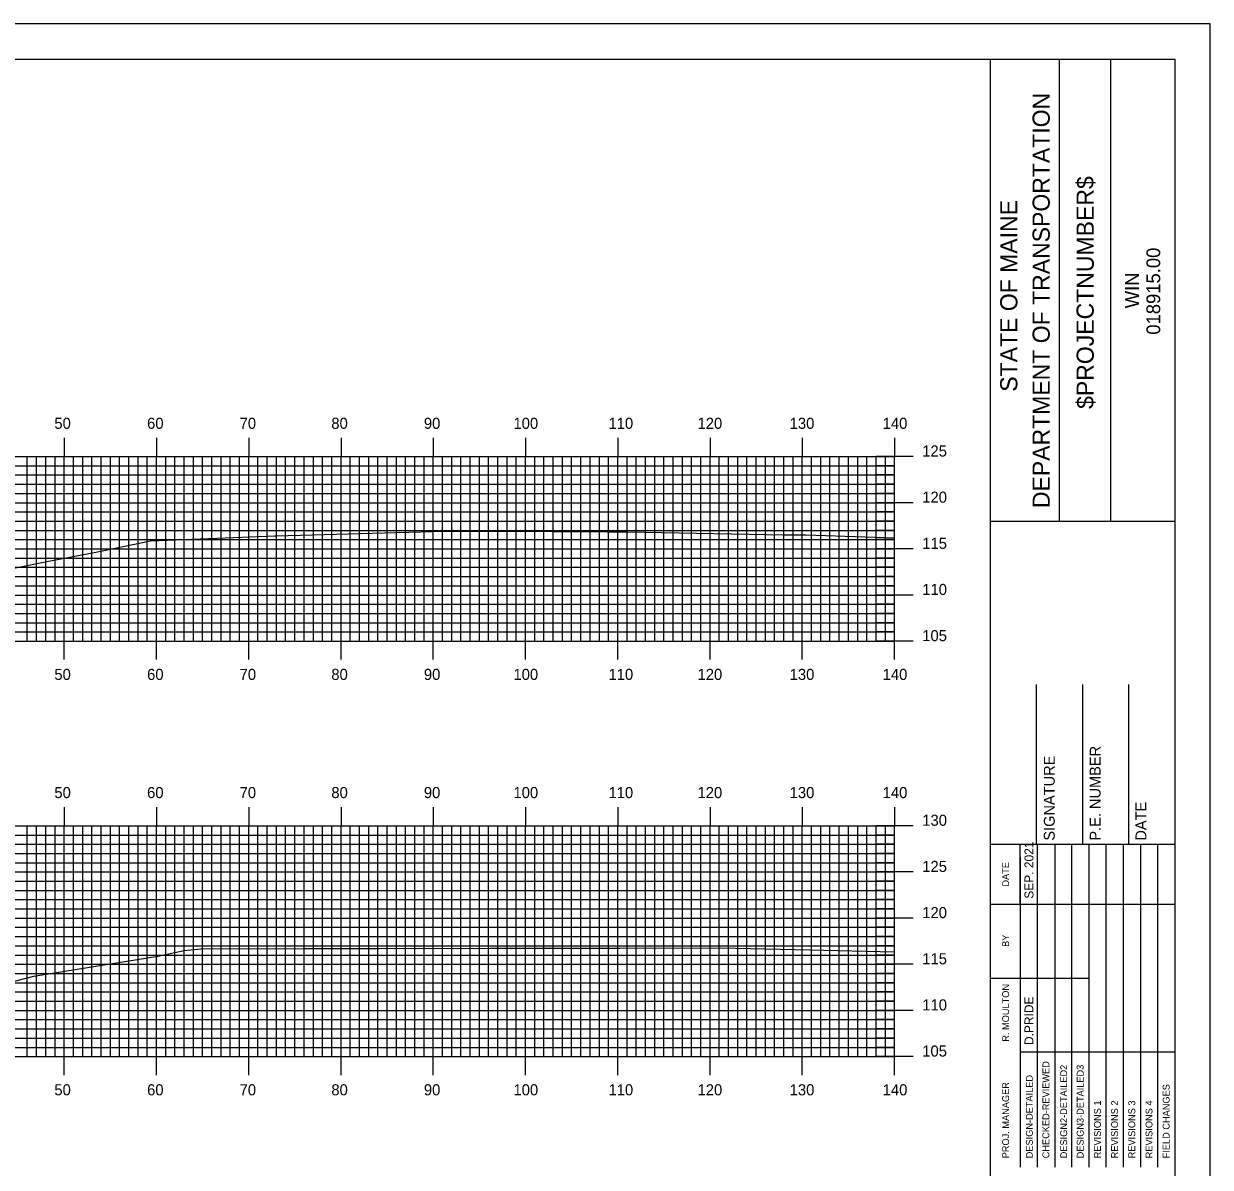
# Model space of a CAD drawing. Extents: x 844536 to 844879, y 363538 to 363758.
# Drawn here: x 844747.6 to 844876.2, y 363633.7 to 363757.6 of the extents above; entities that cross this region are included whole.
import ezdxf

# ---------------------------------------------------------------- set-up
doc = ezdxf.new("R2010")
doc.units = 0
for name, color, linetype in [('BORDER', 7, 'Continuous'), ('H_V ANNOTATION', 7, 'Continuous'), ('MAJOR', 7, 'Continuous'), ('MINOR', 7, 'Continuous'), ('PLOT BOUNDARY', 7, 'Continuous'), ('S_Roadway_Centerline', 7, 'Continuous')]:
    doc.layers.add(name, color=color, linetype=linetype)

msp = doc.modelspace()

# ---------------------------------------------------------------- linework, layer by layer
at = {"layer": 'BORDER'}
for p, q in [((844852.36, 363543.72), (844852.36, 363753.72)), ((844859.82, 363703.72), (844859.82, 363753.72)), ((844865.41, 363703.72), (844865.41, 363753.72)), ((844852.37, 363703.71), (844872.36, 363703.71)), ((844857.36, 363668.73), (844857.36, 363686.02)), ((844862.36, 363668.73), (844862.36, 363686.02)), ((844867.36, 363668.73), (844867.36, 363686.02)), ((844852.36, 363668.73), (844872.36, 363668.73))]:
    msp.add_line(p, q, dxfattribs=at)
msp.add_lwpolyline([(844552.36, 363543.72), (844872.36, 363543.72), (844872.36, 363753.72), (844552.36, 363753.72)], close=True, dxfattribs=at)
for points in [[(844855.59, 363662.23), (844855.59, 363668.73)], [(844857.46, 363633.73), (844857.46, 363668.73)], [(844859.32, 363668.73), (844859.32, 363633.73)], [(844861.19, 363633.73), (844861.19, 363668.73)], [(844863.05, 363633.73), (844863.05, 363668.73)], [(844864.91, 363633.73), (844864.91, 363668.73)], [(844866.78, 363633.73), (844866.78, 363668.73)], [(844868.64, 363633.73), (844868.64, 363668.73)], [(844870.5, 363633.73), (844870.5, 363668.73)], [(844855.6, 363633.73), (844855.6, 363667.31)], [(844852.36, 363662.23), (844872.36, 363662.23)], [(844852.36, 363654.23), (844855.6, 363654.23)], [(844855.59, 363654.23), (844863.05, 363654.23)], [(844855.59, 363646.23), (844872.36, 363646.23)]]:
    msp.add_lwpolyline(points, dxfattribs=at)
at = {"layer": 'MAJOR'}
for p, q in [((844751.96, 363712.73), (844751.96, 363710.72)), ((844761.96, 363712.73), (844761.96, 363710.72)), ((844771.96, 363712.73), (844771.96, 363710.72)), ((844781.96, 363712.73), (844781.96, 363710.72)), ((844791.96, 363712.73), (844791.96, 363710.72)), ((844801.96, 363712.73), (844801.96, 363710.72)), ((844811.96, 363712.73), (844811.96, 363710.72)), ((844821.96, 363712.73), (844821.96, 363710.72)), ((844831.96, 363712.73), (844831.96, 363710.72)), ((844841.96, 363712.73), (844841.96, 363710.72)), ((844561.96, 363710.72), (844841.96, 363710.72)), ((844561.96, 363710.72), (844841.96, 363710.72)), ((844751.96, 363690.72), (844751.96, 363710.72)), ((844761.96, 363690.72), (844761.96, 363710.72)), ((844771.96, 363690.72), (844771.96, 363710.72)), ((844781.96, 363690.72), (844781.96, 363710.72)), ((844791.96, 363690.72), (844791.96, 363710.72)), ((844801.96, 363690.72), (844801.96, 363710.72)), ((844811.96, 363690.72), (844811.96, 363710.72)), ((844821.96, 363690.72), (844821.96, 363710.72)), ((844831.96, 363690.72), (844831.96, 363710.72)), ((844843.97, 363710.72), (844839.96, 363710.72)), ((844841.96, 363690.72), (844841.96, 363710.72)), ((844841.96, 363690.72), (844841.96, 363710.72)), ((844561.96, 363705.72), (844841.96, 363705.72)), ((844843.97, 363705.72), (844839.96, 363705.72)), ((844561.96, 363700.72), (844841.96, 363700.72)), ((844843.97, 363700.72), (844839.96, 363700.72)), ((844561.96, 363695.72), (844841.96, 363695.72)), ((844843.97, 363695.72), (844839.96, 363695.72)), ((844561.96, 363690.72), (844841.96, 363690.72)), ((844561.96, 363690.72), (844841.96, 363690.72)), ((844751.96, 363688.72), (844751.96, 363690.72)), ((844761.96, 363688.72), (844761.96, 363690.72)), ((844771.96, 363688.72), (844771.96, 363690.72)), ((844781.96, 363688.72), (844781.96, 363690.72)), ((844791.96, 363688.72), (844791.96, 363690.72)), ((844801.96, 363688.72), (844801.96, 363690.72)), ((844811.96, 363688.72), (844811.96, 363690.72)), ((844821.96, 363688.72), (844821.96, 363690.72)), ((844831.96, 363688.72), (844831.96, 363690.72)), ((844843.97, 363690.72), (844839.96, 363690.72)), ((844841.96, 363688.72), (844841.96, 363690.72)), ((844751.96, 363672.73), (844751.96, 363670.72)), ((844761.96, 363672.73), (844761.96, 363670.72)), ((844771.96, 363672.73), (844771.96, 363670.72)), ((844781.96, 363672.73), (844781.96, 363670.72)), ((844791.96, 363672.73), (844791.96, 363670.72)), ((844801.96, 363672.73), (844801.96, 363670.72)), ((844811.96, 363672.73), (844811.96, 363670.72)), ((844821.96, 363672.73), (844821.96, 363670.72)), ((844831.96, 363672.73), (844831.96, 363670.72)), ((844841.96, 363672.73), (844841.96, 363670.72)), ((844561.96, 363670.72), (844841.96, 363670.72)), ((844561.96, 363670.72), (844841.96, 363670.72)), ((844751.96, 363645.72), (844751.96, 363670.72)), ((844761.96, 363645.72), (844761.96, 363670.72)), ((844771.96, 363645.72), (844771.96, 363670.72)), ((844781.96, 363645.72), (844781.96, 363670.72)), ((844791.96, 363645.72), (844791.96, 363670.72)), ((844801.96, 363645.72), (844801.96, 363670.72)), ((844811.96, 363645.72), (844811.96, 363670.72)), ((844821.96, 363645.72), (844821.96, 363670.72)), ((844831.96, 363645.72), (844831.96, 363670.72)), ((844843.97, 363670.72), (844839.96, 363670.72)), ((844841.96, 363645.72), (844841.96, 363670.72)), ((844841.96, 363645.72), (844841.96, 363670.72)), ((844561.96, 363665.72), (844841.96, 363665.72)), ((844843.97, 363665.72), (844839.96, 363665.72)), ((844561.96, 363660.72), (844841.96, 363660.72)), ((844843.97, 363660.72), (844839.96, 363660.72)), ((844561.96, 363655.72), (844841.96, 363655.72)), ((844843.97, 363655.72), (844839.96, 363655.72)), ((844561.96, 363650.72), (844841.96, 363650.72)), ((844843.97, 363650.72), (844839.96, 363650.72)), ((844561.96, 363645.72), (844841.96, 363645.72)), ((844561.96, 363645.72), (844841.96, 363645.72)), ((844751.96, 363643.72), (844751.96, 363645.72)), ((844761.96, 363643.72), (844761.96, 363645.72)), ((844771.96, 363643.72), (844771.96, 363645.72)), ((844781.96, 363643.72), (844781.96, 363645.72)), ((844791.96, 363643.72), (844791.96, 363645.72)), ((844801.96, 363643.72), (844801.96, 363645.72)), ((844811.96, 363643.72), (844811.96, 363645.72)), ((844821.96, 363643.72), (844821.96, 363645.72)), ((844831.96, 363643.72), (844831.96, 363645.72)), ((844843.97, 363645.72), (844839.96, 363645.72)), ((844841.96, 363643.72), (844841.96, 363645.72))]:
    msp.add_line(p, q, dxfattribs=at)
at = {"layer": 'MINOR'}
for p, q in [((844747.96, 363690.72), (844747.96, 363710.72)), ((844748.96, 363690.72), (844748.96, 363710.72)), ((844749.96, 363690.72), (844749.96, 363710.72)), ((844750.96, 363690.72), (844750.96, 363710.72)), ((844752.96, 363690.72), (844752.96, 363710.72)), ((844753.96, 363690.72), (844753.96, 363710.72)), ((844754.96, 363690.72), (844754.96, 363710.72)), ((844755.96, 363690.72), (844755.96, 363710.72)), ((844756.96, 363690.72), (844756.96, 363710.72)), ((844757.96, 363690.72), (844757.96, 363710.72)), ((844758.96, 363690.72), (844758.96, 363710.72)), ((844759.96, 363690.72), (844759.96, 363710.72)), ((844760.96, 363690.72), (844760.96, 363710.72)), ((844762.96, 363690.72), (844762.96, 363710.72)), ((844763.96, 363690.72), (844763.96, 363710.72)), ((844764.96, 363690.72), (844764.96, 363710.72)), ((844765.96, 363690.72), (844765.96, 363710.72)), ((844766.96, 363690.72), (844766.96, 363710.72)), ((844767.96, 363690.72), (844767.96, 363710.72)), ((844768.96, 363690.72), (844768.96, 363710.72)), ((844769.96, 363690.72), (844769.96, 363710.72)), ((844770.96, 363690.72), (844770.96, 363710.72)), ((844772.96, 363690.72), (844772.96, 363710.72)), ((844773.96, 363690.72), (844773.96, 363710.72)), ((844774.96, 363690.72), (844774.96, 363710.72)), ((844775.96, 363690.72), (844775.96, 363710.72)), ((844776.96, 363690.72), (844776.96, 363710.72)), ((844777.96, 363690.72), (844777.96, 363710.72)), ((844778.96, 363690.72), (844778.96, 363710.72)), ((844779.96, 363690.72), (844779.96, 363710.72)), ((844780.96, 363690.72), (844780.96, 363710.72)), ((844782.96, 363690.72), (844782.96, 363710.72)), ((844783.96, 363690.72), (844783.96, 363710.72)), ((844784.96, 363690.72), (844784.96, 363710.72)), ((844785.96, 363690.72), (844785.96, 363710.72)), ((844786.96, 363690.72), (844786.96, 363710.72)), ((844787.96, 363690.72), (844787.96, 363710.72)), ((844788.96, 363690.72), (844788.96, 363710.72)), ((844789.96, 363690.72), (844789.96, 363710.72)), ((844790.96, 363690.72), (844790.96, 363710.72)), ((844792.96, 363690.72), (844792.96, 363710.72)), ((844793.96, 363690.72), (844793.96, 363710.72)), ((844794.96, 363690.72), (844794.96, 363710.72)), ((844795.96, 363690.72), (844795.96, 363710.72)), ((844796.96, 363690.72), (844796.96, 363710.72)), ((844797.96, 363690.72), (844797.96, 363710.72)), ((844798.96, 363690.72), (844798.96, 363710.72)), ((844799.96, 363690.72), (844799.96, 363710.72)), ((844800.96, 363690.72), (844800.96, 363710.72)), ((844802.96, 363690.72), (844802.96, 363710.72)), ((844803.96, 363690.72), (844803.96, 363710.72)), ((844804.96, 363690.72), (844804.96, 363710.72)), ((844805.96, 363690.72), (844805.96, 363710.72)), ((844806.96, 363690.72), (844806.96, 363710.72)), ((844807.96, 363690.72), (844807.96, 363710.72)), ((844808.96, 363690.72), (844808.96, 363710.72)), ((844809.96, 363690.72), (844809.96, 363710.72)), ((844810.96, 363690.72), (844810.96, 363710.72)), ((844812.96, 363690.72), (844812.96, 363710.72)), ((844813.96, 363690.72), (844813.96, 363710.72)), ((844814.96, 363690.72), (844814.96, 363710.72)), ((844815.96, 363690.72), (844815.96, 363710.72)), ((844816.96, 363690.72), (844816.96, 363710.72)), ((844817.96, 363690.72), (844817.96, 363710.72)), ((844818.96, 363690.72), (844818.96, 363710.72)), ((844819.96, 363690.72), (844819.96, 363710.72)), ((844820.96, 363690.72), (844820.96, 363710.72)), ((844822.96, 363690.72), (844822.96, 363710.72)), ((844823.96, 363690.72), (844823.96, 363710.72)), ((844824.96, 363690.72), (844824.96, 363710.72)), ((844825.96, 363690.72), (844825.96, 363710.72)), ((844826.96, 363690.72), (844826.96, 363710.72)), ((844827.96, 363690.72), (844827.96, 363710.72)), ((844828.96, 363690.72), (844828.96, 363710.72)), ((844829.96, 363690.72), (844829.96, 363710.72)), ((844830.96, 363690.72), (844830.96, 363710.72)), ((844832.96, 363690.72), (844832.96, 363710.72)), ((844833.96, 363690.72), (844833.96, 363710.72)), ((844834.96, 363690.72), (844834.96, 363710.72)), ((844835.96, 363690.72), (844835.96, 363710.72)), ((844836.96, 363690.72), (844836.96, 363710.72)), ((844837.96, 363690.72), (844837.96, 363710.72)), ((844838.96, 363690.72), (844838.96, 363710.72)), ((844839.96, 363690.72), (844839.96, 363710.72)), ((844840.96, 363690.72), (844840.96, 363710.72)), ((844561.96, 363709.72), (844841.96, 363709.72)), ((844841.96, 363709.72), (844839.96, 363709.72)), ((844561.96, 363708.72), (844841.96, 363708.72)), ((844561.96, 363707.72), (844841.96, 363707.72)), ((844841.96, 363708.72), (844839.96, 363708.72)), ((844841.96, 363707.72), (844839.96, 363707.72)), ((844561.96, 363706.72), (844841.96, 363706.72)), ((844841.96, 363706.72), (844839.96, 363706.72)), ((844561.96, 363704.72), (844841.96, 363704.72)), ((844841.96, 363704.72), (844839.96, 363704.72)), ((844561.96, 363703.72), (844841.96, 363703.72)), ((844561.96, 363702.72), (844841.96, 363702.72)), ((844841.96, 363703.72), (844839.96, 363703.72)), ((844841.96, 363702.72), (844839.96, 363702.72)), ((844561.96, 363701.72), (844841.96, 363701.72)), ((844841.96, 363701.72), (844839.96, 363701.72)), ((844561.96, 363699.72), (844841.96, 363699.72)), ((844561.96, 363698.72), (844841.96, 363698.72)), ((844841.96, 363699.72), (844839.96, 363699.72)), ((844841.96, 363698.72), (844839.96, 363698.72)), ((844561.96, 363697.72), (844841.96, 363697.72)), ((844841.96, 363697.72), (844839.96, 363697.72)), ((844561.96, 363696.72), (844841.96, 363696.72)), ((844841.96, 363696.72), (844839.96, 363696.72)), ((844561.96, 363694.72), (844841.96, 363694.72)), ((844561.96, 363693.72), (844841.96, 363693.72)), ((844841.96, 363694.72), (844839.96, 363694.72)), ((844841.96, 363693.72), (844839.96, 363693.72)), ((844561.96, 363692.72), (844841.96, 363692.72)), ((844841.96, 363692.72), (844839.96, 363692.72)), ((844561.96, 363691.72), (844841.96, 363691.72)), ((844841.96, 363691.72), (844839.96, 363691.72)), ((844747.96, 363645.72), (844747.96, 363670.72)), ((844748.96, 363645.72), (844748.96, 363670.72)), ((844749.96, 363645.72), (844749.96, 363670.72)), ((844750.96, 363645.72), (844750.96, 363670.72)), ((844752.96, 363645.72), (844752.96, 363670.72)), ((844753.96, 363645.72), (844753.96, 363670.72)), ((844754.96, 363645.72), (844754.96, 363670.72)), ((844755.96, 363645.72), (844755.96, 363670.72)), ((844756.96, 363645.72), (844756.96, 363670.72)), ((844757.96, 363645.72), (844757.96, 363670.72)), ((844758.96, 363645.72), (844758.96, 363670.72)), ((844759.96, 363645.72), (844759.96, 363670.72)), ((844760.96, 363645.72), (844760.96, 363670.72)), ((844762.96, 363645.72), (844762.96, 363670.72)), ((844763.96, 363645.72), (844763.96, 363670.72)), ((844764.96, 363645.72), (844764.96, 363670.72)), ((844765.96, 363645.72), (844765.96, 363670.72)), ((844766.96, 363645.72), (844766.96, 363670.72)), ((844767.96, 363645.72), (844767.96, 363670.72)), ((844768.96, 363645.72), (844768.96, 363670.72)), ((844769.96, 363645.72), (844769.96, 363670.72)), ((844770.96, 363645.72), (844770.96, 363670.72)), ((844772.96, 363645.72), (844772.96, 363670.72)), ((844773.96, 363645.72), (844773.96, 363670.72)), ((844774.96, 363645.72), (844774.96, 363670.72)), ((844775.96, 363645.72), (844775.96, 363670.72)), ((844776.96, 363645.72), (844776.96, 363670.72)), ((844777.96, 363645.72), (844777.96, 363670.72)), ((844778.96, 363645.72), (844778.96, 363670.72)), ((844779.96, 363645.72), (844779.96, 363670.72)), ((844780.96, 363645.72), (844780.96, 363670.72)), ((844782.96, 363645.72), (844782.96, 363670.72)), ((844783.96, 363645.72), (844783.96, 363670.72)), ((844784.96, 363645.72), (844784.96, 363670.72)), ((844785.96, 363645.72), (844785.96, 363670.72)), ((844786.96, 363645.72), (844786.96, 363670.72)), ((844787.96, 363645.72), (844787.96, 363670.72)), ((844788.96, 363645.72), (844788.96, 363670.72)), ((844789.96, 363645.72), (844789.96, 363670.72)), ((844790.96, 363645.72), (844790.96, 363670.72)), ((844792.96, 363645.72), (844792.96, 363670.72)), ((844793.96, 363645.72), (844793.96, 363670.72)), ((844794.96, 363645.72), (844794.96, 363670.72)), ((844795.96, 363645.72), (844795.96, 363670.72)), ((844796.96, 363645.72), (844796.96, 363670.72)), ((844797.96, 363645.72), (844797.96, 363670.72)), ((844798.96, 363645.72), (844798.96, 363670.72)), ((844799.96, 363645.72), (844799.96, 363670.72)), ((844800.96, 363645.72), (844800.96, 363670.72)), ((844802.96, 363645.72), (844802.96, 363670.72)), ((844803.96, 363645.72), (844803.96, 363670.72)), ((844804.96, 363645.72), (844804.96, 363670.72)), ((844805.96, 363645.72), (844805.96, 363670.72)), ((844806.96, 363645.72), (844806.96, 363670.72)), ((844807.96, 363645.72), (844807.96, 363670.72)), ((844808.96, 363645.72), (844808.96, 363670.72)), ((844809.96, 363645.72), (844809.96, 363670.72)), ((844810.96, 363645.72), (844810.96, 363670.72)), ((844812.96, 363645.72), (844812.96, 363670.72)), ((844813.96, 363645.72), (844813.96, 363670.72)), ((844814.96, 363645.72), (844814.96, 363670.72)), ((844815.96, 363645.72), (844815.96, 363670.72)), ((844816.96, 363645.72), (844816.96, 363670.72)), ((844817.96, 363645.72), (844817.96, 363670.72)), ((844818.96, 363645.72), (844818.96, 363670.72)), ((844819.96, 363645.72), (844819.96, 363670.72)), ((844820.96, 363645.72), (844820.96, 363670.72)), ((844822.96, 363645.72), (844822.96, 363670.72)), ((844823.96, 363645.72), (844823.96, 363670.72)), ((844824.96, 363645.72), (844824.96, 363670.72)), ((844825.96, 363645.72), (844825.96, 363670.72)), ((844826.96, 363645.72), (844826.96, 363670.72)), ((844827.96, 363645.72), (844827.96, 363670.72)), ((844828.96, 363645.72), (844828.96, 363670.72)), ((844829.96, 363645.72), (844829.96, 363670.72)), ((844830.96, 363645.72), (844830.96, 363670.72)), ((844832.96, 363645.72), (844832.96, 363670.72)), ((844833.96, 363645.72), (844833.96, 363670.72)), ((844834.96, 363645.72), (844834.96, 363670.72)), ((844835.96, 363645.72), (844835.96, 363670.72)), ((844836.96, 363645.72), (844836.96, 363670.72)), ((844837.96, 363645.72), (844837.96, 363670.72)), ((844838.96, 363645.72), (844838.96, 363670.72)), ((844839.96, 363645.72), (844839.96, 363670.72)), ((844840.96, 363645.72), (844840.96, 363670.72)), ((844561.96, 363669.72), (844841.96, 363669.72)), ((844841.96, 363669.72), (844839.96, 363669.72)), ((844561.96, 363668.72), (844841.96, 363668.72)), ((844841.96, 363668.72), (844839.96, 363668.72)), ((844561.96, 363667.72), (844841.96, 363667.72)), ((844561.96, 363666.72), (844841.96, 363666.72)), ((844841.96, 363667.72), (844839.96, 363667.72)), ((844841.96, 363666.72), (844839.96, 363666.72)), ((844561.96, 363664.72), (844841.96, 363664.72)), ((844841.96, 363664.72), (844839.96, 363664.72)), ((844561.96, 363663.72), (844841.96, 363663.72)), ((844561.96, 363662.72), (844841.96, 363662.72)), ((844841.96, 363663.72), (844839.96, 363663.72)), ((844841.96, 363662.72), (844839.96, 363662.72)), ((844561.96, 363661.72), (844841.96, 363661.72)), ((844841.96, 363661.72), (844839.96, 363661.72)), ((844561.96, 363659.72), (844841.96, 363659.72)), ((844841.96, 363659.72), (844839.96, 363659.72)), ((844561.96, 363658.72), (844841.96, 363658.72)), ((844561.96, 363657.72), (844841.96, 363657.72)), ((844841.96, 363658.72), (844839.96, 363658.72)), ((844841.96, 363657.72), (844839.96, 363657.72)), ((844561.96, 363656.72), (844841.96, 363656.72)), ((844841.96, 363656.72), (844839.96, 363656.72)), ((844561.96, 363654.72), (844841.96, 363654.72)), ((844561.96, 363653.72), (844841.96, 363653.72)), ((844841.96, 363654.72), (844839.96, 363654.72)), ((844841.96, 363653.72), (844839.96, 363653.72)), ((844561.96, 363652.72), (844841.96, 363652.72)), ((844841.96, 363652.72), (844839.96, 363652.72)), ((844561.96, 363651.72), (844841.96, 363651.72)), ((844841.96, 363651.72), (844839.96, 363651.72)), ((844561.96, 363649.72), (844841.96, 363649.72)), ((844561.96, 363648.72), (844841.96, 363648.72)), ((844841.96, 363649.72), (844839.96, 363649.72)), ((844841.96, 363648.72), (844839.96, 363648.72)), ((844561.96, 363647.72), (844841.96, 363647.72)), ((844841.96, 363647.72), (844839.96, 363647.72)), ((844561.96, 363646.72), (844841.96, 363646.72)), ((844841.96, 363646.72), (844839.96, 363646.72))]:
    msp.add_line(p, q, dxfattribs=at)
at = {"layer": 'PLOT BOUNDARY'}
msp.add_lwpolyline([(844536.18, 363537.6), (844876.18, 363537.6), (844876.18, 363757.6), (844536.18, 363757.6)], close=True, dxfattribs=at)
at = {"layer": 'S_Roadway_Centerline'}
for points in [[(844745.08, 363698.35), (844750.07, 363699.35), (844755.19, 363700.32), (844761.32, 363701.59), (844774.78, 363702.13), (844774.84, 363702.13), (844774.86, 363702.13), (844774.94, 363702.14), (844793.23, 363702.64), (844799, 363702.62), (844810.8, 363702.57), (844811.47, 363702.56), (844811.8, 363702.56), (844812.91, 363702.55), (844830, 363702.24), (844832.35, 363702.23), (844841.96, 363701.92)], [(844742.77, 363652.92), (844748.68, 363654.43), (844762.12, 363656.59), (844764.97, 363657.22), (844766.78, 363657.39), (844778.03, 363657.42), (844786.14, 363657.42), (844798.09, 363657.45), (844799.08, 363657.48), (844804.61, 363657.48), (844812.2, 363657.45), (844823.11, 363657.5), (844832.77, 363657.29), (844841.9, 363657.07), (844841.96, 363657.07)]]:
    msp.add_lwpolyline(points, dxfattribs=at)

# ---------------------------------------------------------------- texts
at = {"layer": 'BORDER'}
for s, height, p in [('DEPARTMENT OF TRANSPORTATION', 1.8635, (844858.78, 363705.13)), ('$PROJECTNUMBER$', 1.8635, (844863.55, 363715.88)), ('STATE OF MAINE', 1.8635, (844855.27, 363717.74)), ('018915.00', 1.491, (844870.75, 363723.92)), ('WIN', 1.491, (844868.44, 363726.78)), ('SIGNATURE', 1.181, (844859.32, 363669.11)), ('P.E. NUMBER', 1.1811, (844864.29, 363669.11)), ('DATE', 1.181, (844869.25, 363669.11)), ('SEP. 2021', 0.969, (844857.01, 363662.82)), ('DATE', 0.743, (844854.37, 363664.14)), ('BY', 0.743, (844854.37, 363657.6)), ('R. MOULTON', 0.745, (844854.37, 363647.33)), ('D.PRIDE', 0.969, (844857.01, 363646.97)), ('CHECKED-REVIEWED', 0.7455, (844858.73, 363634.7)), ('DESIGN2-DETAILED2', 0.7455, (844860.66, 363634.7)), ('DESIGN3-DETAILED3', 0.7455, (844862.45, 363634.7)), ('DESIGN-DETAILED', 0.7455, (844856.94, 363634.7)), ('PROJ. MANAGER', 0.7455, (844854.37, 363634.7)), ('FIELD CHANGES', 0.7455, (844871.77, 363634.7)), ('REVISIONS 1', 0.7455, (844864.32, 363634.7)), ('REVISIONS 2', 0.7455, (844866.18, 363634.7)), ('REVISIONS 3', 0.7455, (844868.04, 363634.7)), ('REVISIONS 4', 0.7455, (844869.91, 363634.7))]:
    msp.add_text(s, height=height, rotation=90, dxfattribs=at).set_placement(p)
at = {"layer": 'H_V ANNOTATION'}
for s, p in [('50', (844750.89, 363713.72)), ('60', (844760.94, 363713.72)), ('70', (844770.97, 363713.72)), ('80', (844780.91, 363713.72)), ('90', (844790.94, 363713.72)), ('100', (844800.65, 363713.72)), ('110', (844810.95, 363713.72)), ('120', (844820.6, 363713.72)), ('130', (844830.59, 363713.72)), ('140', (844840.67, 363713.72)), ('125', (844844.96, 363710.72)), ('120', (844844.96, 363705.72)), ('115', (844844.96, 363700.72)), ('110', (844844.96, 363695.72)), ('105', (844844.96, 363690.72)), ('50', (844750.89, 363686.52)), ('60', (844760.94, 363686.52)), ('70', (844770.97, 363686.52)), ('80', (844780.91, 363686.52)), ('90', (844790.94, 363686.52)), ('100', (844800.65, 363686.52)), ('110', (844810.95, 363686.52)), ('120', (844820.6, 363686.52)), ('130', (844830.59, 363686.52)), ('140', (844840.67, 363686.52)), ('50', (844750.89, 363673.72)), ('60', (844760.94, 363673.72)), ('70', (844770.97, 363673.72)), ('80', (844780.91, 363673.72)), ('90', (844790.94, 363673.72)), ('100', (844800.65, 363673.72)), ('110', (844810.95, 363673.72)), ('120', (844820.6, 363673.72)), ('130', (844830.59, 363673.72)), ('140', (844840.67, 363673.72)), ('130', (844844.96, 363670.72)), ('125', (844844.96, 363665.72)), ('120', (844844.96, 363660.72)), ('115', (844844.96, 363655.72)), ('110', (844844.96, 363650.72)), ('105', (844844.96, 363645.72)), ('50', (844750.89, 363641.52)), ('60', (844760.94, 363641.52)), ('70', (844770.97, 363641.52)), ('80', (844780.91, 363641.52)), ('90', (844790.94, 363641.52)), ('100', (844800.65, 363641.52)), ('110', (844810.95, 363641.52)), ('120', (844820.6, 363641.52)), ('130', (844830.59, 363641.52)), ('140', (844840.67, 363641.52))]:
    msp.add_text(s, height=1.2, dxfattribs=at).set_placement(p)

doc.saveas('drawing.dxf')
